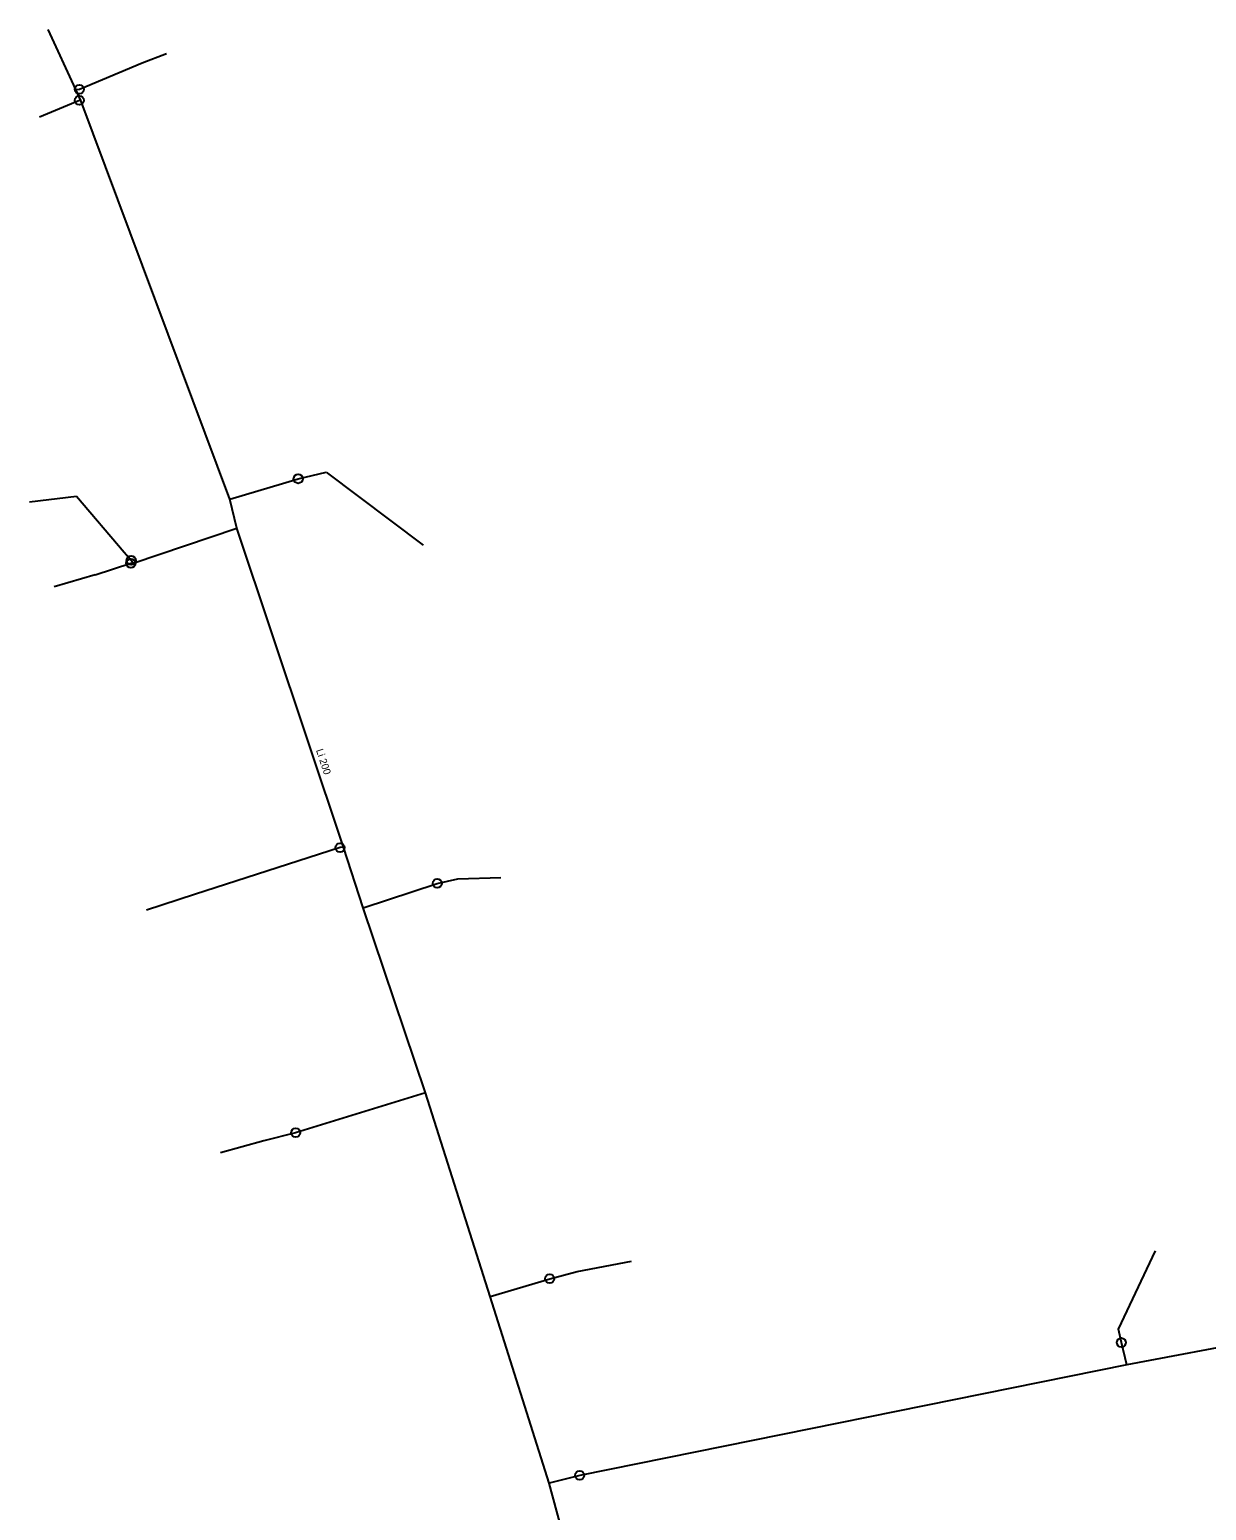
# Model space of a CAD drawing. Extents: x -684835 to -684548, y -1163297 to -1162881.
# Drawn here: x -684834.8 to -684770.1, y -1163230 to -1163148.5 of the extents above; entities that cross this region are included whole.
import ezdxf

# ---------------------------------------------------------------- set-up
doc = ezdxf.new("R2010")
doc.units = 0
for name, color, linetype in [('Popis vodovodních řadů', 7, 'Continuous'), ('Vod přípojky-voda pitná', 7, 'Continuous'), ('Vodovodní řad', 7, 'Continuous'), ('Vodovodní šoupata', 7, 'Continuous')]:
    doc.layers.add(name, color=color, linetype=linetype)

msp = doc.modelspace()

# ---------------------------------------------------------------- linework, layer by layer
at = {"layer": 'Vod přípojky-voda pitná'}
for points in [[(-684832.27, -1163151.8), (-684832.08, -1163151.78), (-684828.62, -1163150.33)], [(-684828.62, -1163150.33), (-684827.28, -1163149.81)], [(-684832, -1163152.4), (-684832.08, -1163152.39), (-684834.271, -1163153.311)], [(-684823.8, -1163174.33), (-684820.04, -1163173.21), (-684818.51, -1163172.84)], [(-684818.51, -1163172.84), (-684813.17, -1163176.86)], [(-684832.24, -1163174.18), (-684834.82, -1163174.49)], [(-684829.13, -1163177.85), (-684829.23, -1163177.7), (-684829.62, -1163177.27), (-684832.24, -1163174.18)], [(-684831.21, -1163178.49), (-684829.25, -1163177.86), (-684829.13, -1163177.85), (-684823.42, -1163175.93)], [(-684831.21, -1163178.49), (-684833.47, -1163179.15)], [(-684817.54, -1163193.48), (-684817.74, -1163193.5), (-684825.75, -1163196.09)], [(-684811.25, -1163195.22), (-684808.89, -1163195.14)], [(-684816.46, -1163196.81), (-684812.39, -1163195.47), (-684811.25, -1163195.22)], [(-684825.75, -1163196.09), (-684828.38, -1163196.95)], [(-684813.04, -1163207), (-684820.18, -1163209.19), (-684821.93, -1163209.64)], [(-684821.93, -1163209.64), (-684824.32, -1163210.29)], [(-684804.69, -1163216.82), (-684801.7, -1163216.25)], [(-684774.91, -1163219.99), (-684772.87, -1163215.69)], [(-684809.47, -1163218.2), (-684806.2, -1163217.22), (-684804.69, -1163216.82)], [(-684774.44, -1163221.96), (-684774.74, -1163220.73), (-684774.91, -1163219.99)]]:
    msp.add_lwpolyline(points, dxfattribs=at)
at = {"layer": 'Vodovodní řad'}
for points in [[(-684806.23, -1163228.47), (-684809.47, -1163218.2), (-684813.04, -1163207), (-684816.46, -1163196.81), (-684817.54, -1163193.48), (-684823.42, -1163175.93), (-684823.8, -1163174.33), (-684832, -1163152.4), (-684832.27, -1163151.8), (-684833.799, -1163148.497)], [(-684726.98, -1163212.7), (-684737.85, -1163214.74), (-684752.81, -1163217.88), (-684774.44, -1163221.96), (-684804.55, -1163228.04)], [(-684804.55, -1163228.04), (-684806.23, -1163228.47)], [(-684795.33, -1163270.32), (-684795.91, -1163268.04), (-684799.82, -1163252.11), (-684806.23, -1163228.47)]]:
    msp.add_lwpolyline(points, dxfattribs=at)
at = {"layer": 'Vodovodní šoupata'}
for centre in [(-684832.08, -1163151.78), (-684832.08, -1163152.39), (-684820.04, -1163173.21), (-684829.25, -1163177.86), (-684829.23, -1163177.7), (-684817.74, -1163193.5), (-684812.39, -1163195.47), (-684820.18, -1163209.19), (-684806.2, -1163217.22), (-684774.74, -1163220.73), (-684804.55, -1163228.04)]:
    msp.add_circle(centre, 0.25, dxfattribs=at)

# ---------------------------------------------------------------- texts
at = {"layer": 'Popis vodovodních řadů'}
msp.add_text('Li 200', height=0.4, rotation=288.52305, dxfattribs=at).set_placement((-684819.065, -1163188.143))

doc.saveas('drawing.dxf')
